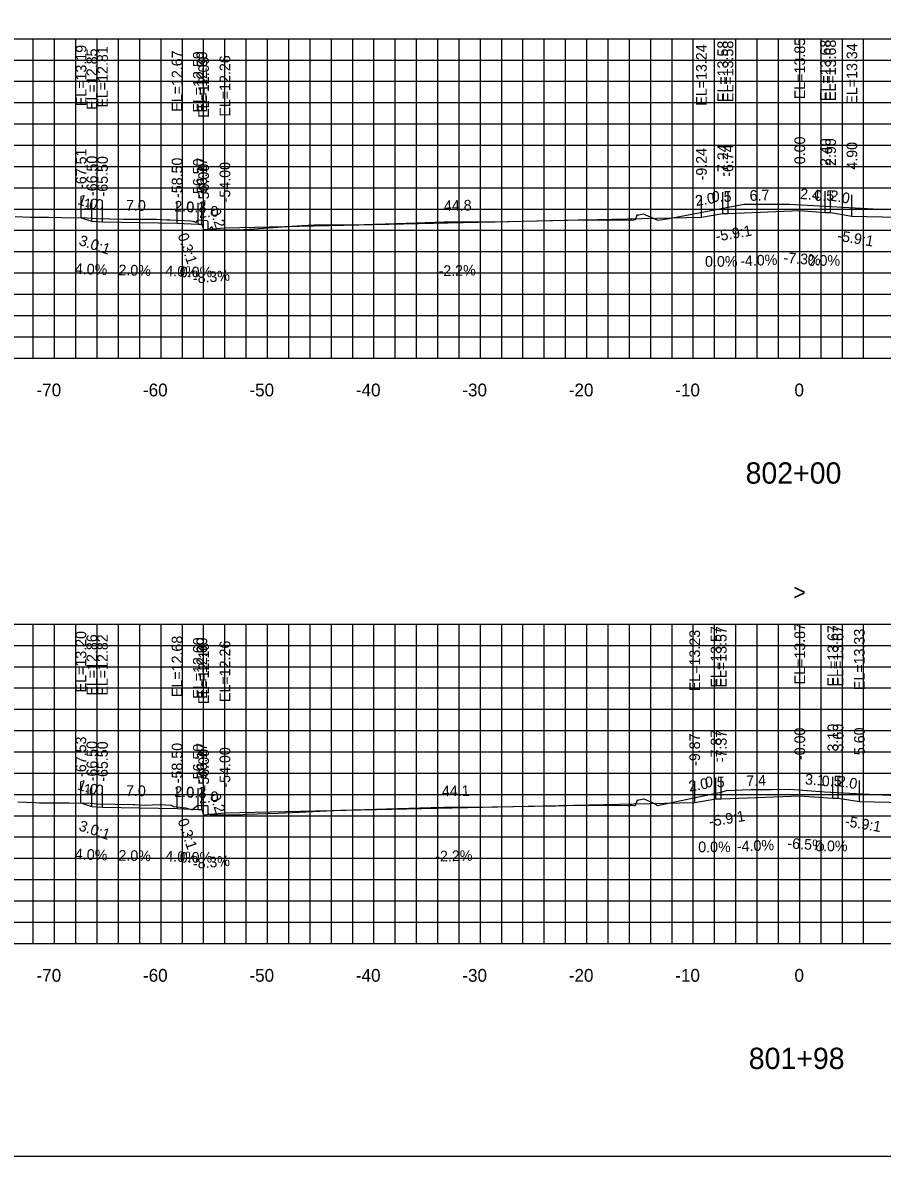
# Model space of a CAD drawing. Extents: x 1797419 to 1809236, y 248759 to 251512.
# Drawn here: x 1802558 to 1802638.8, y 250417.3 to 250523.8 of the extents above; entities that cross this region are included whole.
import ezdxf

# ---------------------------------------------------------------- set-up
doc = ezdxf.new("R2010")
doc.units = 0
for name, color, linetype in [('1', 7, 'Continuous'), ('10', 7, 'Continuous'), ('3', 7, 'Continuous'), ('4', 7, 'Continuous'), ('60', 7, 'Continuous'), ('CL-CNST', 7, 'Continuous'), ('Level 62', 7, 'Continuous'), ('M-ROADS', 7, 'Continuous')]:
    doc.layers.add(name, color=color, linetype=linetype)

msp = doc.modelspace()

# ---------------------------------------------------------------- linework, layer by layer
for p, q in [((1802563.49, 250505.44), (1802563.49, 250507.44)), ((1802621.76, 250505.5), (1802621.76, 250507.5)), ((1802623.76, 250505.84), (1802623.76, 250507.84)), ((1802624.26, 250505.84), (1802624.26, 250507.84)), ((1802631, 250506.11), (1802631, 250508.11)), ((1802633.4, 250505.93), (1802633.4, 250507.93)), ((1802633.9, 250505.93), (1802633.9, 250507.93)), ((1802635.9, 250505.59), (1802635.9, 250507.59)), ((1802564.5, 250505.11), (1802564.5, 250507.11)), ((1802565.5, 250505.07), (1802565.5, 250507.07)), ((1802572.5, 250504.93), (1802572.5, 250506.93)), ((1802574.5, 250504.85), (1802574.5, 250506.85)), ((1802574.83, 250504.85), (1802574.83, 250506.85)), ((1802575, 250504.35), (1802575, 250506.35)), ((1802577, 250504.51), (1802577, 250506.51)), ((1802631, 250451.12), (1802631, 250453.12)), ((1802563.47, 250450.46), (1802563.47, 250452.46)), ((1802564.5, 250450.11), (1802564.5, 250452.11)), ((1802565.5, 250450.07), (1802565.5, 250452.07)), ((1802621.13, 250450.49), (1802621.13, 250452.49)), ((1802623.13, 250450.83), (1802623.13, 250452.83)), ((1802623.63, 250450.83), (1802623.63, 250452.83)), ((1802634.1, 250450.92), (1802634.1, 250452.92)), ((1802634.6, 250450.92), (1802634.6, 250452.92)), ((1802636.6, 250450.58), (1802636.6, 250452.58)), ((1802572.5, 250449.93), (1802572.5, 250451.93)), ((1802574.5, 250449.85), (1802574.5, 250451.85)), ((1802574.83, 250449.85), (1802574.83, 250451.85)), ((1802575, 250449.35), (1802575, 250451.35)), ((1802577, 250449.52), (1802577, 250451.52))]:
    msp.add_line(p, q)
msp.add_lwpolyline([(1802481, 250417.26), (1802781, 250417.26), (1802781, 250607.26), (1802481, 250607.26)], close=True)
at = {"layer": '60'}
for p, q in [((1802481, 250492.26), (1802781, 250492.26)), ((1802561, 250492.2), (1802561, 250492.26)), ((1802571, 250492.2), (1802571, 250492.26)), ((1802581, 250492.2), (1802581, 250492.26)), ((1802591, 250492.2), (1802591, 250492.26)), ((1802601, 250492.2), (1802601, 250492.26)), ((1802611, 250492.2), (1802611, 250492.26)), ((1802621, 250492.2), (1802621, 250492.26)), ((1802631, 250492.2), (1802631, 250492.26)), ((1802481, 250437.26), (1802781, 250437.26)), ((1802561, 250437.2), (1802561, 250437.26)), ((1802571, 250437.2), (1802571, 250437.26)), ((1802581, 250437.2), (1802581, 250437.26)), ((1802591, 250437.2), (1802591, 250437.26)), ((1802601, 250437.2), (1802601, 250437.26)), ((1802611, 250437.2), (1802611, 250437.26)), ((1802621, 250437.2), (1802621, 250437.26)), ((1802631, 250437.2), (1802631, 250437.26))]:
    msp.add_line(p, q, dxfattribs=at)
at = {"layer": 'CL-CNST'}
for points in [[(1802563.49, 250505.44), (1802564.5, 250505.11), (1802565.5, 250505.07), (1802572.5, 250504.93), (1802574.5, 250504.85), (1802574.83, 250504.85), (1802575, 250504.35), (1802577, 250504.51), (1802621.76, 250505.5), (1802623.76, 250505.84), (1802624.26, 250505.84), (1802631, 250506.11), (1802633.4, 250505.93), (1802633.9, 250505.93), (1802635.9, 250505.59), (1802697, 250504.25), (1802699, 250504.08), (1802699.17, 250504.58), (1802699.5, 250504.58), (1802701.5, 250504.66), (1802706.5, 250504.76), (1802707.5, 250504.8), (1802709.18, 250505.36)], [(1802563.47, 250450.46), (1802564.5, 250450.11), (1802565.5, 250450.07), (1802572.5, 250449.93), (1802574.5, 250449.85), (1802574.83, 250449.85), (1802575, 250449.35), (1802577, 250449.52), (1802621.13, 250450.49), (1802623.13, 250450.83), (1802623.63, 250450.83), (1802631, 250451.12), (1802634.1, 250450.92), (1802634.6, 250450.92), (1802636.6, 250450.58), (1802697, 250449.26), (1802699, 250449.09), (1802699.17, 250449.59), (1802699.5, 250449.59), (1802701.5, 250449.67), (1802706.5, 250449.77), (1802707.5, 250449.81), (1802709.18, 250450.37)]]:
    msp.add_lwpolyline(points, dxfattribs=at)
at = {"layer": 'Level 62'}
for p, q in [((1802481, 250522.26), (1802781, 250522.26)), ((1802559, 250492.26), (1802559, 250522.26)), ((1802561, 250492.26), (1802561, 250522.26)), ((1802563, 250492.26), (1802563, 250522.26)), ((1802565, 250492.26), (1802565, 250522.26)), ((1802567, 250492.26), (1802567, 250522.26)), ((1802569, 250492.26), (1802569, 250522.26)), ((1802571, 250492.26), (1802571, 250522.26)), ((1802573, 250492.26), (1802573, 250522.26)), ((1802575, 250492.26), (1802575, 250522.26)), ((1802577, 250492.26), (1802577, 250522.26)), ((1802579, 250492.26), (1802579, 250522.26)), ((1802581, 250492.26), (1802581, 250522.26)), ((1802583, 250492.26), (1802583, 250522.26)), ((1802585, 250492.26), (1802585, 250522.26)), ((1802587, 250492.26), (1802587, 250522.26)), ((1802589, 250492.26), (1802589, 250522.26)), ((1802591, 250492.26), (1802591, 250522.26)), ((1802593, 250492.26), (1802593, 250522.26)), ((1802595, 250492.26), (1802595, 250522.26)), ((1802597, 250492.26), (1802597, 250522.26)), ((1802599, 250492.26), (1802599, 250522.26)), ((1802601, 250492.26), (1802601, 250522.26)), ((1802603, 250492.26), (1802603, 250522.26)), ((1802605, 250492.26), (1802605, 250522.26)), ((1802607, 250492.26), (1802607, 250522.26)), ((1802609, 250492.26), (1802609, 250522.26)), ((1802611, 250492.26), (1802611, 250522.26)), ((1802613, 250492.26), (1802613, 250522.26)), ((1802615, 250492.26), (1802615, 250522.26)), ((1802617, 250492.26), (1802617, 250522.26)), ((1802619, 250492.26), (1802619, 250522.26)), ((1802621, 250492.26), (1802621, 250522.26)), ((1802623, 250492.26), (1802623, 250522.26)), ((1802625, 250492.26), (1802625, 250522.26)), ((1802627, 250492.26), (1802627, 250522.26)), ((1802629, 250492.26), (1802629, 250522.26)), ((1802631, 250492.26), (1802631, 250522.26)), ((1802633, 250492.26), (1802633, 250522.26)), ((1802635, 250492.26), (1802635, 250522.26)), ((1802637, 250492.26), (1802637, 250522.26)), ((1802481, 250520.26), (1802781, 250520.26)), ((1802481, 250518.26), (1802781, 250518.26)), ((1802481, 250516.26), (1802781, 250516.26)), ((1802481, 250514.26), (1802781, 250514.26)), ((1802481, 250512.26), (1802781, 250512.26)), ((1802481, 250510.26), (1802781, 250510.26)), ((1802481, 250508.26), (1802781, 250508.26)), ((1802481, 250506.26), (1802781, 250506.26)), ((1802481, 250504.26), (1802781, 250504.26)), ((1802481, 250502.26), (1802781, 250502.26)), ((1802481, 250500.26), (1802781, 250500.26)), ((1802481, 250498.26), (1802781, 250498.26)), ((1802481, 250496.26), (1802781, 250496.26)), ((1802481, 250494.26), (1802781, 250494.26)), ((1802481, 250492.26), (1802781, 250492.26)), ((1802481, 250467.26), (1802781, 250467.26)), ((1802559, 250437.26), (1802559, 250467.26)), ((1802561, 250437.26), (1802561, 250467.26)), ((1802563, 250437.26), (1802563, 250467.26)), ((1802565, 250437.26), (1802565, 250467.26)), ((1802567, 250437.26), (1802567, 250467.26)), ((1802569, 250437.26), (1802569, 250467.26)), ((1802571, 250437.26), (1802571, 250467.26)), ((1802573, 250437.26), (1802573, 250467.26)), ((1802575, 250437.26), (1802575, 250467.26)), ((1802577, 250437.26), (1802577, 250467.26)), ((1802579, 250437.26), (1802579, 250467.26)), ((1802581, 250437.26), (1802581, 250467.26)), ((1802583, 250437.26), (1802583, 250467.26)), ((1802585, 250437.26), (1802585, 250467.26)), ((1802587, 250437.26), (1802587, 250467.26)), ((1802589, 250437.26), (1802589, 250467.26)), ((1802591, 250437.26), (1802591, 250467.26)), ((1802593, 250437.26), (1802593, 250467.26)), ((1802595, 250437.26), (1802595, 250467.26)), ((1802597, 250437.26), (1802597, 250467.26)), ((1802599, 250437.26), (1802599, 250467.26)), ((1802601, 250437.26), (1802601, 250467.26)), ((1802603, 250437.26), (1802603, 250467.26)), ((1802605, 250437.26), (1802605, 250467.26)), ((1802607, 250437.26), (1802607, 250467.26)), ((1802609, 250437.26), (1802609, 250467.26)), ((1802611, 250437.26), (1802611, 250467.26)), ((1802613, 250437.26), (1802613, 250467.26)), ((1802615, 250437.26), (1802615, 250467.26)), ((1802617, 250437.26), (1802617, 250467.26)), ((1802619, 250437.26), (1802619, 250467.26)), ((1802621, 250437.26), (1802621, 250467.26)), ((1802623, 250437.26), (1802623, 250467.26)), ((1802625, 250437.26), (1802625, 250467.26)), ((1802627, 250437.26), (1802627, 250467.26)), ((1802629, 250437.26), (1802629, 250467.26)), ((1802631, 250437.26), (1802631, 250467.26)), ((1802633, 250437.26), (1802633, 250467.26)), ((1802635, 250437.26), (1802635, 250467.26)), ((1802637, 250437.26), (1802637, 250467.26)), ((1802481, 250465.26), (1802781, 250465.26)), ((1802481, 250463.26), (1802781, 250463.26)), ((1802481, 250461.26), (1802781, 250461.26)), ((1802481, 250459.26), (1802781, 250459.26)), ((1802481, 250457.26), (1802781, 250457.26)), ((1802481, 250455.26), (1802781, 250455.26)), ((1802481, 250453.26), (1802781, 250453.26)), ((1802481, 250451.26), (1802781, 250451.26)), ((1802481, 250449.26), (1802781, 250449.26)), ((1802481, 250447.26), (1802781, 250447.26)), ((1802481, 250445.26), (1802781, 250445.26)), ((1802481, 250443.26), (1802781, 250443.26)), ((1802481, 250441.26), (1802781, 250441.26)), ((1802481, 250439.26), (1802781, 250439.26)), ((1802481, 250437.26), (1802781, 250437.26))]:
    msp.add_line(p, q, dxfattribs=at)
at = {"layer": 'M-ROADS'}
for points in [[(1802557.31, 250505.55), (1802558.74, 250505.5), (1802558.96, 250505.49), (1802560.46, 250505.49), (1802561.66, 250505.48), (1802564.07, 250505.43), (1802564.89, 250505.37), (1802567.48, 250505.32), (1802568.09, 250505.32), (1802570.33, 250505.32), (1802570.44, 250505.31), (1802570.59, 250505.32), (1802571.53, 250505.26), (1802571.65, 250505.26), (1802571.85, 250505.26), (1802573.79, 250505.15), (1802574.05, 250505.09), (1802574.08, 250505.13), (1802574.3, 250504.99), (1802574.33, 250505.08), (1802574.35, 250505.1), (1802574.37, 250505.13), (1802574.38, 250505.16), (1802574.39, 250505.16), (1802574.39, 250505.17), (1802574.4, 250505.18), (1802574.4, 250505.19), (1802574.41, 250505.19), (1802574.41, 250505.19), (1802574.42, 250505.2), (1802574.45, 250505.24), (1802574.73, 250505.22), (1802574.77, 250505.14), (1802574.89, 250505.2), (1802575.34, 250505.19), (1802575.39, 250505.05), (1802575.39, 250504.33), (1802575.39, 250504.33), (1802575.4, 250504.33), (1802575.42, 250504.33), (1802575.5, 250504.33), (1802575.78, 250504.62), (1802575.85, 250504.32), (1802576.85, 250504.31), (1802578.37, 250504.32), (1802584.22, 250504.72), (1802585.37, 250504.77), (1802587.5, 250504.77), (1802589.1, 250504.77), (1802594.03, 250504.93), (1802597.58, 250505.06), (1802599.43, 250505.06), (1802601.92, 250505.06), (1802601.98, 250505.06), (1802602.38, 250505.06), (1802610.17, 250505.24), (1802611.61, 250505.25), (1802612.4, 250505.25), (1802612.58, 250505.24), (1802612.89, 250505.22), (1802612.97, 250505.23), (1802614.05, 250505.24), (1802614.49, 250505.24), (1802615.02, 250505.23), (1802615.09, 250505.23), (1802615.11, 250505.24), (1802615.12, 250505.34), (1802615.12, 250505.24), (1802615.12, 250505.24), (1802615.13, 250505.23), (1802615.13, 250505.25), (1802615.14, 250505.25), (1802615.24, 250505.23), (1802615.58, 250505.28), (1802615.73, 250505.73), (1802615.8, 250505.74), (1802615.81, 250505.67), (1802615.81, 250505.72), (1802615.82, 250505.69), (1802615.89, 250505.73), (1802616.29, 250505.81), (1802617.67, 250505.22), (1802618.73, 250505.38), (1802625.75, 250506.73), (1802627.21, 250506.73), (1802629.15, 250506.73), (1802630.05, 250506.71), (1802639.01, 250506.22)], [(1802557.56, 250450.56), (1802559.18, 250450.49), (1802559.58, 250450.48), (1802562.36, 250450.48), (1802564.34, 250450.44), (1802565.01, 250450.39), (1802568.37, 250450.32), (1802568.41, 250450.32), (1802568.55, 250450.32), (1802569.56, 250450.26), (1802570.15, 250450.28), (1802570.93, 250450.32), (1802571.91, 250450.26), (1802571.99, 250450.26), (1802572.16, 250450.12), (1802573.34, 250449.99), (1802573.93, 250449.82), (1802574.05, 250449.95), (1802574.46, 250450.26), (1802574.73, 250450.23), (1802574.77, 250450.16), (1802574.87, 250450.22), (1802575.35, 250450.21), (1802575.39, 250450.09), (1802575.39, 250449.46), (1802575.64, 250449.34), (1802577.71, 250449.34), (1802578.03, 250449.33), (1802578.24, 250449.33), (1802579.05, 250449.39), (1802582, 250449.51), (1802587.89, 250449.78), (1802588.01, 250449.78), (1802596.34, 250450.04), (1802597.61, 250450.07), (1802599.19, 250450.06), (1802599.77, 250450.06), (1802600.21, 250450.06), (1802602.09, 250450.09), (1802608.1, 250450.2), (1802610.19, 250450.25), (1802612.15, 250450.26), (1802612.39, 250450.26), (1802612.78, 250450.25), (1802613, 250450.24), (1802613.44, 250450.24), (1802614.86, 250450.23), (1802615.05, 250450.23), (1802615.11, 250450.26), (1802615.12, 250450.34), (1802615.12, 250450.25), (1802615.12, 250450.25), (1802615.13, 250450.25), (1802615.15, 250450.25), (1802615.16, 250450.25), (1802615.48, 250450.22), (1802615.58, 250450.23), (1802615.75, 250450.75), (1802615.8, 250450.75), (1802615.81, 250450.69), (1802615.81, 250450.74), (1802615.82, 250450.71), (1802615.88, 250450.74), (1802616.35, 250450.84), (1802617.36, 250450.4), (1802617.62, 250450.22), (1802623.72, 250451.5), (1802624.13, 250451.62), (1802626.43, 250451.73), (1802627.55, 250451.73), (1802628.39, 250451.73), (1802630.06, 250451.74), (1802633.31, 250451.49), (1802636.88, 250451.33), (1802641.93, 250451.05)]]:
    msp.add_lwpolyline(points, dxfattribs=at)

# ---------------------------------------------------------------- texts
for s, rotation, p in [('-5.9:1', 9.648, (1802623.18, 250503.2)), ('-5.9:1', 350.352, (1802634.48, 250503.3)), ('3.0:1', 341.5651, (1802563.21, 250502.9)), ('0.3:1', 288.4353, (1802572.55, 250503.81)), ('3.0:1', 341.5651, (1802563.2, 250447.91)), ('0.3:1', 288.4353, (1802572.55, 250448.81)), ('-5.9:1', 9.648, (1802622.55, 250448.2)), ('-5.9:1', 350.352, (1802635.18, 250448.29))]:
    msp.add_text(s, height=1, rotation=rotation).set_placement(p)
at = {"layer": '1'}
for s, p in [('802+00', (1802625.91, 250480.46)), ('801+98', (1802626.21, 250425.46))]:
    msp.add_text(s, height=2, dxfattribs=at).set_placement(p)
at = {"layer": '10'}
for s, p in [('-70', (1802559.3, 250488.66)), ('-60', (1802569.3, 250488.66)), ('-50', (1802579.3, 250488.66)), ('-40', (1802589.3, 250488.66)), ('-30', (1802599.3, 250488.66)), ('-20', (1802609.3, 250488.66)), ('-10', (1802619.3, 250488.66)), ('0', (1802630.5, 250488.66)), ('-70', (1802559.3, 250433.66)), ('-60', (1802569.3, 250433.66)), ('-50', (1802579.3, 250433.66)), ('-40', (1802589.3, 250433.66)), ('-30', (1802599.3, 250433.66)), ('-20', (1802609.3, 250433.66)), ('-10', (1802619.3, 250433.66)), ('0', (1802630.5, 250433.66))]:
    msp.add_text(s, height=1.2, dxfattribs=at).set_placement(p)
at = {"layer": '3'}
for s, p in [('EL=13.85', (1802631.5, 250516.58)), ('EL=13.19', (1802563.99, 250515.92)), ('EL=12.85', (1802565, 250515.58)), ('EL=12.81', (1802566, 250515.79)), ('EL=13.24', (1802622.26, 250515.97)), ('EL=13.58', (1802624.26, 250516.31)), ('EL=13.58', (1802624.76, 250516.31)), ('EL=13.68', (1802633.9, 250516.41)), ('EL=13.68', (1802634.4, 250516.41)), ('EL=13.34', (1802636.4, 250516.07)), ('EL=12.67', (1802573, 250515.4)), ('EL=12.59', (1802575, 250515.32)), ('EL=12.59', (1802575.33, 250515.32)), ('EL=12.09', (1802575.5, 250514.82)), ('EL=12.26', (1802577.5, 250514.94)), ('0.00', (1802631.5, 250510.47)), ('2.40', (1802633.9, 250510.3)), ('2.90', (1802634.4, 250510.3)), ('-67.51', (1802563.99, 250508.15)), ('-9.24', (1802622.26, 250508.95)), ('-7.24', (1802624.26, 250509.29)), ('-6.74', (1802624.76, 250509.29)), ('4.90', (1802636.4, 250509.96)), ('-66.50', (1802565, 250507.48)), ('-65.50', (1802566, 250507.44)), ('-58.50', (1802573, 250507.3)), ('-56.50', (1802575, 250507.22)), ('-56.17', (1802575.33, 250507.3)), ('-54.00', (1802577.5, 250506.89)), ('-56.00', (1802575.5, 250506.72)), ('EL=13.57', (1802623.63, 250461.3)), ('EL=13.57', (1802624.13, 250461.3)), ('EL=13.87', (1802631.5, 250461.6)), ('EL=13.67', (1802634.6, 250461.4)), ('EL=13.67', (1802635.1, 250461.4)), ('EL=13.20', (1802563.97, 250460.85)), ('EL=12.86', (1802565, 250460.54)), ('EL=12.82', (1802566, 250460.54)), ('EL=12.68', (1802573, 250460.4)), ('EL=12.60', (1802575, 250460.25)), ('EL=12.60', (1802575.33, 250460.25)), ('EL=13.23', (1802621.63, 250460.96)), ('EL=13.33', (1802637.1, 250461.06)), ('EL=12.10', (1802575.5, 250459.75)), ('EL=12.26', (1802577.5, 250459.94)), ('-0.00', (1802631.5, 250454.49)), ('3.10', (1802634.6, 250455.29)), ('3.60', (1802635.1, 250455.29)), ('5.60', (1802637.1, 250454.95)), ('-67.53', (1802563.97, 250452.91)), ('-66.50', (1802565, 250452.49)), ('-9.87', (1802621.63, 250453.94)), ('-7.87', (1802623.63, 250454.28)), ('-7.37', (1802624.13, 250454.28)), ('-65.50', (1802566, 250452.45)), ('-58.50', (1802573, 250452.31)), ('-56.50', (1802575, 250452.23)), ('-56.17', (1802575.33, 250452.31)), ('-56.00', (1802575.5, 250451.73)), ('-54.00', (1802577.5, 250451.9))]:
    msp.add_text(s, height=1, rotation=90, dxfattribs=at).set_placement(p)
at = {"layer": '4'}
for s, rotation, p in [('1.0', 341.5651, (1802563.09, 250506.74)), ('2.0', 9.648, (1802621.27, 250506.53)), ('6.7', 2.2906, (1802626.31, 250507.02)), ('2.4', 355.849, (1802631, 250507.21)), ('2.0', 350.352, (1802633.78, 250507.07)), ('1.0', 357.7094, (1802563.73, 250506.24)), ('7.0', 358.8542, (1802567.7, 250506.12)), ('2.0', 357.7094, (1802572.23, 250506.04)), ('2.0', 4.7636, (1802574.59, 250505.42)), ('0.2', 288.4353, (1802575.56, 250506.16)), ('44.8', 1.2603, (1802597.58, 250506.07)), ('-4.0%', 2.2906, (1802625.42, 250500.88)), ('-7.3%', 355.849, (1802629.44, 250501.21)), ('4.0%', 357.7094, (1802562.89, 250500.17)), ('2.0%', 358.8542, (1802566.99, 250500.04)), ('4.0%', 357.7094, (1802571.39, 250499.97)), ('-2.2%', 1.2603, (1802597.08, 250499.95)), ('-8.3%', 4.7636, (1802574.02, 250499.25)), ('7.4', 2.2906, (1802625.99, 250452.03)), ('3.1', 356.2907, (1802631.47, 250452.2)), ('2.0', 350.352, (1802634.48, 250452.06)), ('1.0', 341.5651, (1802563.08, 250451.75)), ('1.0', 357.7094, (1802563.73, 250451.24)), ('7.0', 358.8542, (1802567.7, 250451.13)), ('2.0', 357.7094, (1802572.23, 250451.04)), ('44.1', 1.2603, (1802597.39, 250451.07)), ('2.0', 9.648, (1802620.64, 250451.52)), ('2.0', 4.7636, (1802574.59, 250450.42)), ('0.2', 288.4353, (1802575.56, 250451.17)), ('-4.0%', 2.2906, (1802625.11, 250445.88)), ('-6.5%', 356.2907, (1802629.82, 250446.19)), ('4.0%', 357.7094, (1802562.89, 250445.17)), ('2.0%', 358.8542, (1802566.99, 250445.04)), ('4.0%', 357.7094, (1802571.39, 250444.97)), ('-2.2%', 1.2603, (1802596.77, 250444.95)), ('-8.3%', 4.7636, (1802574.02, 250444.25))]:
    msp.add_text(s, height=1, rotation=rotation, dxfattribs=at).set_placement(p)
for s, p in [('0.5', (1802622.73, 250506.94)), ('0.5', (1802632.37, 250507.03)), ('0.3', (1802573.39, 250505.95)), ('0.0%', (1802622.1, 250500.84)), ('0.0%', (1802631.74, 250500.93)), ('0.0%', (1802572.76, 250499.85)), ('0.5', (1802633.07, 250452.02)), ('0.3', (1802573.39, 250450.95)), ('0.5', (1802622.09, 250451.93)), ('0.0%', (1802621.46, 250445.83)), ('0.0%', (1802632.44, 250445.92)), ('0.0%', (1802572.76, 250444.85))]:
    msp.add_text(s, height=1, dxfattribs=at).set_placement(p)
at = {"layer": '60'}
msp.add_text('>', height=1.5, dxfattribs=at).set_placement((1802630.39, 250469.51))

doc.saveas('drawing.dxf')
